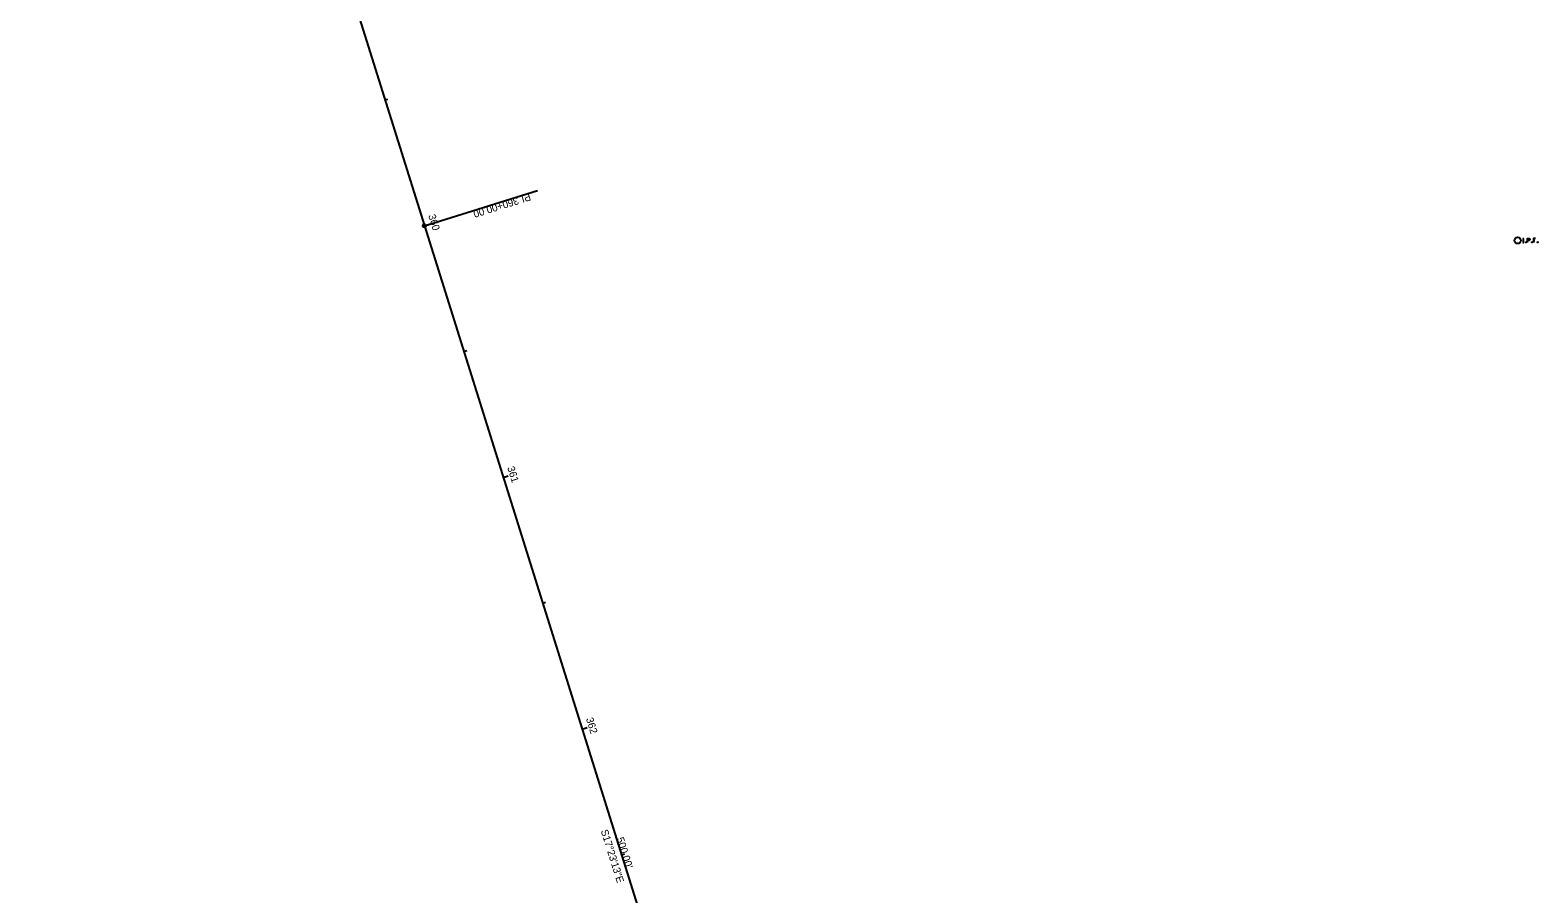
# Model space of a CAD drawing. Extents: x 1918148 to 1920349, y 624677 to 627727.
# Drawn here: x 1919017 to 1919588, y 625880 to 626208 of the extents above; entities that cross this region are included whole.
import ezdxf

# ---------------------------------------------------------------- set-up
doc = ezdxf.new("R2010")
doc.units = 0
for name, color, linetype in [('_CIVIL_CONSTRUCTION', 7, 'Continuous'), ('RS_Raster1', 7, 'Continuous'), ('RW_X_CL', 7, 'Continuous'), ('RW_X_CL_100_Cardinal_Points', 7, 'Continuous'), ('RW_X_CL_100_Curve_Data', 7, 'Continuous'), ('SV_X_Mon_Cells_Found', 7, 'Continuous')]:
    doc.layers.add(name, color=color, linetype=linetype)

msp = doc.modelspace()

# ---------------------------------------------------------------- linework, layer by layer
at = {"layer": 'RS_Raster1'}
for p, q in [((1919016.77, 626610.92), (1919166.18, 626133.77)), ((1919166.18, 626133.77), (1919315.59, 625656.61))]:
    msp.add_line(p, q, dxfattribs=at)
at = {"layer": 'RW_X_CL'}
msp.add_line((1919166.18, 626133.77), (1919209.12, 626147.21), dxfattribs=at)
msp.add_circle((1919166.18, 626133.77), 0.6, dxfattribs=at)
at = {"layer": 'RW_X_CL_100_Cardinal_Points'}
for p, q in [((1919151.24, 626181.48), (1919152.38, 626181.84)), ((1919166.18, 626133.77), (1919168.09, 626134.37)), ((1919181.12, 626086.05), (1919182.27, 626086.41)), ((1919196.06, 626038.34), (1919197.97, 626038.93)), ((1919211, 625990.62), (1919212.15, 625990.98)), ((1919225.94, 625942.91), (1919227.85, 625943.5)), ((1919240.89, 625895.19), (1919242.03, 625895.55))]:
    msp.add_line(p, q, dxfattribs=at)
at = {"layer": 'SV_X_Mon_Cells_Found'}
for points in [[(1919582.57, 626129), (1919582.92, 626129)], [(1919582.75, 626127.4), (1919582.75, 626129)], [(1919584.31, 626127.4), (1919584.31, 626129), (1919584.84, 626129), (1919584.9, 626128.99), (1919584.97, 626128.97), (1919585.01, 626128.94), (1919585.04, 626128.92), (1919585.08, 626128.85), (1919585.12, 626128.79), (1919585.14, 626128.69), (1919585.14, 626128.54), (1919585.13, 626128.49), (1919585.1, 626128.41), (1919585.06, 626128.32), (1919585.02, 626128.29), (1919584.98, 626128.26), (1919584.93, 626128.24), (1919584.84, 626128.22), (1919584.31, 626128.22)], [(1919587.32, 626129), (1919586.56, 626129), (1919586.56, 626127.4)], [(1919582.57, 626127.4), (1919582.92, 626127.4)], [(1919583.7, 626127.62), (1919583.76, 626127.62), (1919583.79, 626127.59), (1919583.83, 626127.54), (1919583.83, 626127.48), (1919583.79, 626127.43), (1919583.76, 626127.4), (1919583.7, 626127.4), (1919583.67, 626127.43), (1919583.64, 626127.48), (1919583.64, 626127.54), (1919583.67, 626127.59), (1919583.7, 626127.62)], [(1919585.95, 626127.62), (1919586.01, 626127.62), (1919586.04, 626127.59), (1919586.07, 626127.54), (1919586.07, 626127.48), (1919586.04, 626127.43), (1919586.01, 626127.4), (1919585.95, 626127.4), (1919585.92, 626127.43), (1919585.89, 626127.48), (1919585.89, 626127.54), (1919585.92, 626127.59), (1919585.95, 626127.62)], [(1919586.56, 626128.22), (1919587.1, 626128.22)], [(1919588.1, 626127.62), (1919588.16, 626127.62), (1919588.19, 626127.59), (1919588.22, 626127.54), (1919588.22, 626127.48), (1919588.19, 626127.43), (1919588.16, 626127.4), (1919588.1, 626127.4), (1919588.07, 626127.43), (1919588.04, 626127.48), (1919588.04, 626127.54), (1919588.07, 626127.59), (1919588.1, 626127.62)]]:
    msp.add_lwpolyline(points, dxfattribs=at)
msp.add_circle((1919580.55, 626128.2), 1.2, dxfattribs=at)

# ---------------------------------------------------------------- texts
at = {"layer": '_CIVIL_CONSTRUCTION'}
msp.add_text('S17°23\'13"E', height=2.8, rotation=287.387, dxfattribs=at).set_placement((1919233, 625904.32))
at = {"layer": 'RW_X_CL'}
for s, p in [('PI', (1919205.99, 626146.19)), ('360+00.00', (1919201.43, 626144.76))]:
    msp.add_text(s, height=2.8, rotation=197.387, dxfattribs=at).set_placement(p)
at = {"layer": 'RW_X_CL_100_Cardinal_Points'}
for s, p in [('360', (1919167.63, 626137.66)), ('361', (1919197.56, 626042.07)), ('362', (1919227.4, 625946.79))]:
    msp.add_text(s, height=2.8, rotation=287.387, dxfattribs=at).set_placement(p)
at = {"layer": 'RW_X_CL_100_Curve_Data'}
msp.add_text("500.00'", height=2.8, rotation=287.387, dxfattribs=at).set_placement((1919238.99, 625901.39))

doc.saveas('drawing.dxf')
